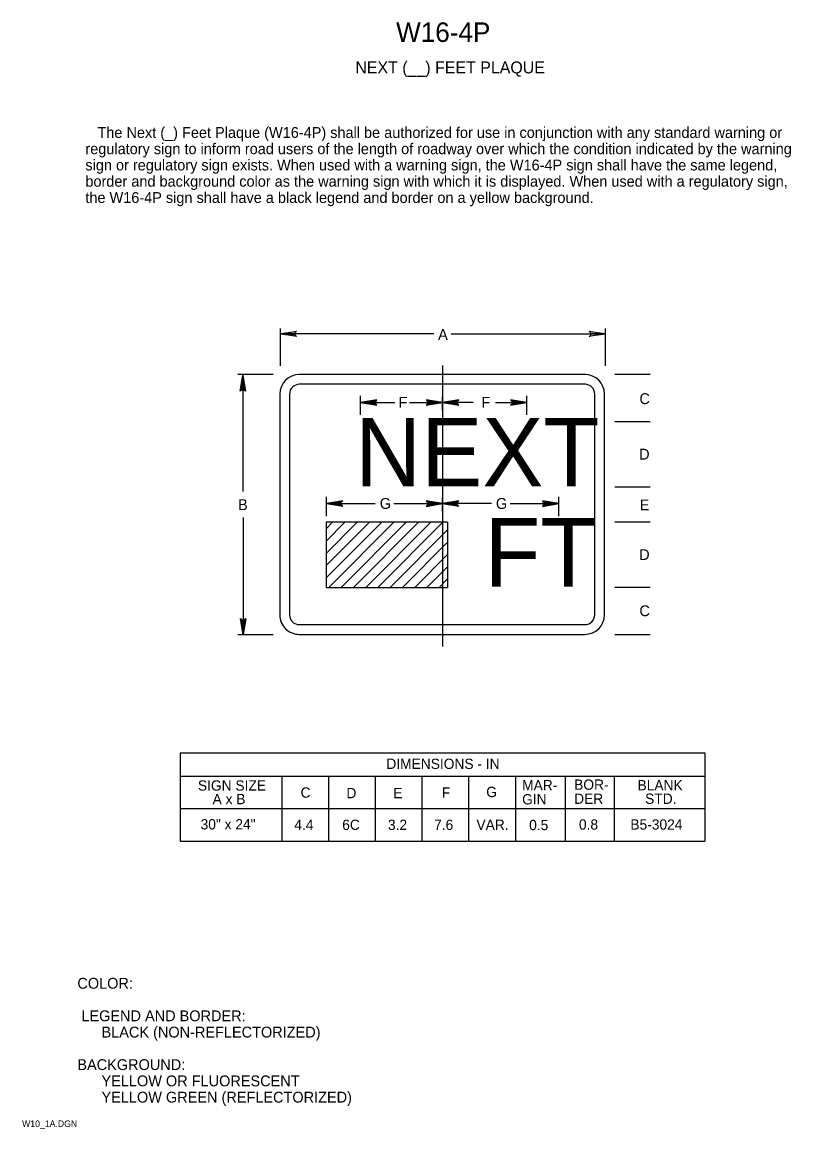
# Model space of a CAD drawing. Extents: x 0.013 to 0.19, y 0.004 to 0.259.
import ezdxf

# ---------------------------------------------------------------- set-up
doc = ezdxf.new("R2010")
doc.units = 0
for name, color, linetype in [('1', 7, 'Continuous'), ('2', 7, 'Continuous'), ('3', 7, 'Continuous')]:
    doc.layers.add(name, color=color, linetype=linetype)

# ---------------------------------------------------------------- blocks, each defined once
blk = doc.blocks.new('RARROW')
at = {"layer": '3'}
for p, q in [((-2.156, 0.285), (-2.2665, 0.384625)), ((-2.2665, 0.384625), (0, 0)), ((0, 0), (-2.2665, -0.379125)), ((-2.156, 0.285), (-2.075625, 0.12075)), ((0, 0), (-2.156, 0.285)), ((-2.14975, -0.2705), (0, 0)), ((-2.075625, 0.12075), (0, 0)), ((0, 0), (-2.074, -0.108)), ((-2.2665, -0.379125), (-2.14975, -0.2705)), ((-2.074, -0.108), (-2.14975, -0.2705))]:
    blk.add_line(p, q, dxfattribs=at)

msp = doc.modelspace()

# ---------------------------------------------------------------- linework, layer by layer
at = {"layer": '1'}
for p, q in [((0.10961, 0.17989), (0.10961, 0.11516)), ((0.08275, 0.14377), (0.08275, 0.12877)), ((0.08275, 0.13095), (0.09558, 0.14377)), ((0.08275, 0.13378), (0.09275, 0.14377)), ((0.08275, 0.13661), (0.08992, 0.14377)), ((0.08275, 0.13943), (0.08709, 0.14377)), ((0.08275, 0.14226), (0.08426, 0.14377)), ((0.0834, 0.12877), (0.0984, 0.14377)), ((0.08623, 0.12877), (0.10123, 0.14377)), ((0.08906, 0.12877), (0.10406, 0.14377)), ((0.09189, 0.12877), (0.10689, 0.14377)), ((0.09472, 0.12877), (0.10972, 0.14377)), ((0.11079, 0.14377), (0.11079, 0.12877)), ((0.09755, 0.12877), (0.11079, 0.14201)), ((0.10037, 0.12877), (0.11079, 0.13919)), ((0.1032, 0.12877), (0.11079, 0.13636)), ((0.10603, 0.12877), (0.11079, 0.13353)), ((0.10886, 0.12877), (0.11079, 0.1307))]:
    msp.add_line(p, q, dxfattribs=at)
at = {"layer": '3'}
for p, q in [((0.0722, 0.17983), (0.0722, 0.18845)), ((0.10763, 0.1872), (0.07224, 0.1872)), ((0.11157, 0.1872), (0.1472, 0.1872)), ((0.1472, 0.17983), (0.1472, 0.18845)), ((0.1472, 0.17983), (0.1472, 0.18845)), ((0.07057, 0.17783), (0.06236, 0.17783)), ((0.06361, 0.1509), (0.06361, 0.17783)), ((0.14266, 0.17783), (0.07657, 0.17783)), ((0.15755, 0.17783), (0.14934, 0.17783)), ((0.1426, 0.17558), (0.07657, 0.17558)), ((0.07207, 0.17333), (0.07207, 0.12243)), ((0.07432, 0.17333), (0.07432, 0.12243)), ((0.09072, 0.16851), (0.09072, 0.17293)), ((0.09072, 0.17138), (0.0986, 0.17138)), ((0.10202, 0.17138), (0.10961, 0.17138)), ((0.10961, 0.16959), (0.10961, 0.17262)), ((0.11671, 0.17138), (0.10961, 0.17138)), ((0.12184, 0.17138), (0.12906, 0.17138)), ((0.12906, 0.16851), (0.12906, 0.17293)), ((0.14472, 0.12243), (0.14472, 0.17333)), ((0.14697, 0.12243), (0.14697, 0.17333)), ((0.15755, 0.1669), (0.14934, 0.1669)), ((0.15755, 0.1519), (0.14934, 0.1519)), ((0.08283, 0.1452), (0.08283, 0.14962)), ((0.08283, 0.14807), (0.09406, 0.14807)), ((0.09837, 0.14807), (0.10961, 0.14807)), ((0.10961, 0.14627), (0.10961, 0.14931)), ((0.12095, 0.14807), (0.10961, 0.14807)), ((0.12518, 0.14807), (0.13641, 0.14807)), ((0.13641, 0.1452), (0.13641, 0.14962)), ((0.06361, 0.14485), (0.06361, 0.11783)), ((0.11079, 0.14377), (0.08275, 0.14377)), ((0.15755, 0.14377), (0.14934, 0.14377)), ((0.08275, 0.12877), (0.11079, 0.12877)), ((0.15755, 0.12877), (0.14934, 0.12877)), ((0.07657, 0.12018), (0.14247, 0.12018)), ((0.07057, 0.11783), (0.06236, 0.11783)), ((0.07657, 0.11793), (0.14247, 0.11793)), ((0.15755, 0.11783), (0.14934, 0.11783)), ((0.04907, 0.09066), (0.04907, 0.07028)), ((0.04907, 0.09066), (0.17016, 0.09066)), ((0.17016, 0.09066), (0.17016, 0.07028)), ((0.04907, 0.08528), (0.17016, 0.08528)), ((0.07257, 0.08528), (0.07257, 0.07028)), ((0.08332, 0.08528), (0.08332, 0.07028)), ((0.09407, 0.08528), (0.09407, 0.07028)), ((0.10482, 0.08528), (0.10482, 0.07028)), ((0.11557, 0.08528), (0.11557, 0.07028)), ((0.12644, 0.08528), (0.12644, 0.07028)), ((0.13789, 0.08528), (0.13789, 0.07028)), ((0.14923, 0.08528), (0.14923, 0.07028)), ((0.04907, 0.07778), (0.17016, 0.07778)), ((0.04907, 0.07028), (0.17016, 0.07028))]:
    msp.add_line(p, q, dxfattribs=at)
for centre, radius, start, end in [((0.0766, 0.1733), 0.00453, 89.6411, 179.6411), ((0.14247, 0.17333), 0.0045, 0, 90), ((0.0766, 0.1733), 0.00228, 89.2872, 179.2872), ((0.14247, 0.17333), 0.00225, 0, 90), ((0.0766, 0.12246), 0.00453, 180.4082, 270.4082), ((0.0766, 0.12246), 0.00228, 180.8112, 270.8112), ((0.14247, 0.12243), 0.0045, 270, 0), ((0.14247, 0.12243), 0.00225, 270, 0)]:
    msp.add_arc(centre, radius, start, end, dxfattribs=at)

# ---------------------------------------------------------------- block references
at = {"layer": '3', "xscale": 0.0016545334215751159}
for p, yscale, rotation in [((0.0722, 0.18721), 0.0016366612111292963, 180), ((0.06357, 0.17771), 0.0016366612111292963, 90), ((0.09072, 0.17138), -0.0016366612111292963, 180), ((0.10961, 0.17138), -0.0016366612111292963, 180), ((0.08283, 0.14807), -0.0016366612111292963, 180), ((0.10961, 0.14807), -0.0016366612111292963, 180), ((0.06361, 0.11783), 0.0016366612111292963, -90)]:
    msp.add_blockref('RARROW', p, dxfattribs=dict(at, yscale=yscale, rotation=rotation))
for p, yscale in [((0.1472, 0.1872), 0.0016366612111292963), ((0.10961, 0.17138), -0.0016366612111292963), ((0.12906, 0.17138), -0.0016366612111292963), ((0.10961, 0.14807), -0.0016366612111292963), ((0.13641, 0.14807), -0.0016366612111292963)]:
    msp.add_blockref('RARROW', p, dxfattribs=dict(at, yscale=yscale))

# ---------------------------------------------------------------- texts
at = {"layer": '1'}
for s, height, p in [('W16-4P', 0.0045, (0.09891, 0.2545)), ('NEXT (__) FEET PLAQUE', 0.0027503, (0.0895, 0.24725)), ('COLOR:', 0.0025, (0.02538, 0.03625)), (' LEGEND AND BORDER:', 0.0024998, (0.02538, 0.02875)), ('      BLACK (NON-REFLECTORIZED)', 0.0024998, (0.02538, 0.025)), ('BACKGROUND:', 0.0024998, (0.02538, 0.0175)), ('      YELLOW OR FLUORESCENT ', 0.0024998, (0.02538, 0.01375)), ('      YELLOW GREEN (REFLECTORIZED)', 0.0024998, (0.02538, 0.01)), ('W10_1A.DGN', 0.0015, (0.01263, 0.00438))]:
    msp.add_text(s, height=height, dxfattribs=at).set_placement(p)
at = {"layer": '2'}
for s, height, p in [('   The Next (_) Feet Plaque (W16-4P) shall be authorized for use in conjunction with any standard warning or ', 0.00249975, (0.02723, 0.23238)), ('regulatory sign to inform road users of the length of roadway over which the condition indicated by the warning ', 0.00249975, (0.02723, 0.22863)), ('sign or regulatory sign exists. When used with a warning sign, the W16-4P sign shall have the same legend, ', 0.00249975, (0.02723, 0.22488)), ('border and background color as the warning sign with which it is displayed. When used with a regulatory sign, ', 0.00249975, (0.02723, 0.22113)), ('the W16-4P sign shall have a black legend and border on a yellow background. ', 0.0024998, (0.02723, 0.21738))]:
    msp.add_text(s, height=height, dxfattribs=at).set_placement(p)
at = {"layer": '3'}
for s, height, p in [('A', 0.0025, (0.1086, 0.18583)), ('C', 0.0025, (0.15504, 0.17102)), ('NEXT', 0.0158, (0.08944, 0.15204)), ('D', 0.0025, (0.15497, 0.15822)), ('B', 0.0025, (0.06245, 0.14658)), ('E', 0.0025, (0.1551, 0.14652)), ('FT', 0.0158, (0.11929, 0.12893)), ('D', 0.0025, (0.15497, 0.13507)), ('C', 0.0025, (0.15504, 0.12212)), ('DIMENSIONS - IN', 0.0023752, (0.09666, 0.08691)), ('SIGN SIZE', 0.002375, (0.05319, 0.08191)), ('MAR-', 0.002375, (0.12798, 0.08198)), ('BOR-', 0.002375, (0.13998, 0.08211)), ('BLANK', 0.002375, (0.1546, 0.08198)), ('C', 0.00238, (0.07687, 0.08028)), ('D', 0.00238, (0.08744, 0.08016)), ('E', 0.00238, (0.09826, 0.08016)), ('F', 0.00238, (0.10944, 0.08028)), ('G', 0.00238, (0.1197, 0.08042)), ('A x B', 0.002375, (0.05657, 0.07878)), ('GIN', 0.002375, (0.12798, 0.07873)), ('DER', 0.002375, (0.13998, 0.07886)), ('STD.', 0.002375, (0.15635, 0.07886)), ('30" x 24"', 0.002375, (0.05381, 0.07297)), ('4.4', 0.002375, (0.07542, 0.07285)), ('6C', 0.002375, (0.08648, 0.07285)), ('3.2', 0.002375, (0.09703, 0.07285)), ('7.6', 0.002375, (0.10768, 0.07285)), ('VAR.', 0.002375, (0.11744, 0.07285)), ('0.5', 0.002375, (0.1296, 0.0728)), ('0.8', 0.002375, (0.14108, 0.07292)), ('B5-3024', 0.002375, (0.15295, 0.07292))]:
    msp.add_text(s, height=height, dxfattribs=at).set_placement(p)
for s, p in [('F', (0.09948, 0.17017)), ('F', (0.11858, 0.17017)), ('G', (0.09513, 0.14686)), ('G', (0.12193, 0.14686))]:
    msp.add_text(s, height=0.0025, rotation=360, dxfattribs=at).set_placement(p)

doc.saveas('drawing.dxf')
